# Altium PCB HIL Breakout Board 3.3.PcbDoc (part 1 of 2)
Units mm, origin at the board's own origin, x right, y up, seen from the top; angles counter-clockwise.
Board outline 262.51 x 133.53 mm, 4 copper layers (Top Layer, InternalPlane, Power, Bottom Layer); 38 components, 129 nets, 1004 pads, 22 vias.
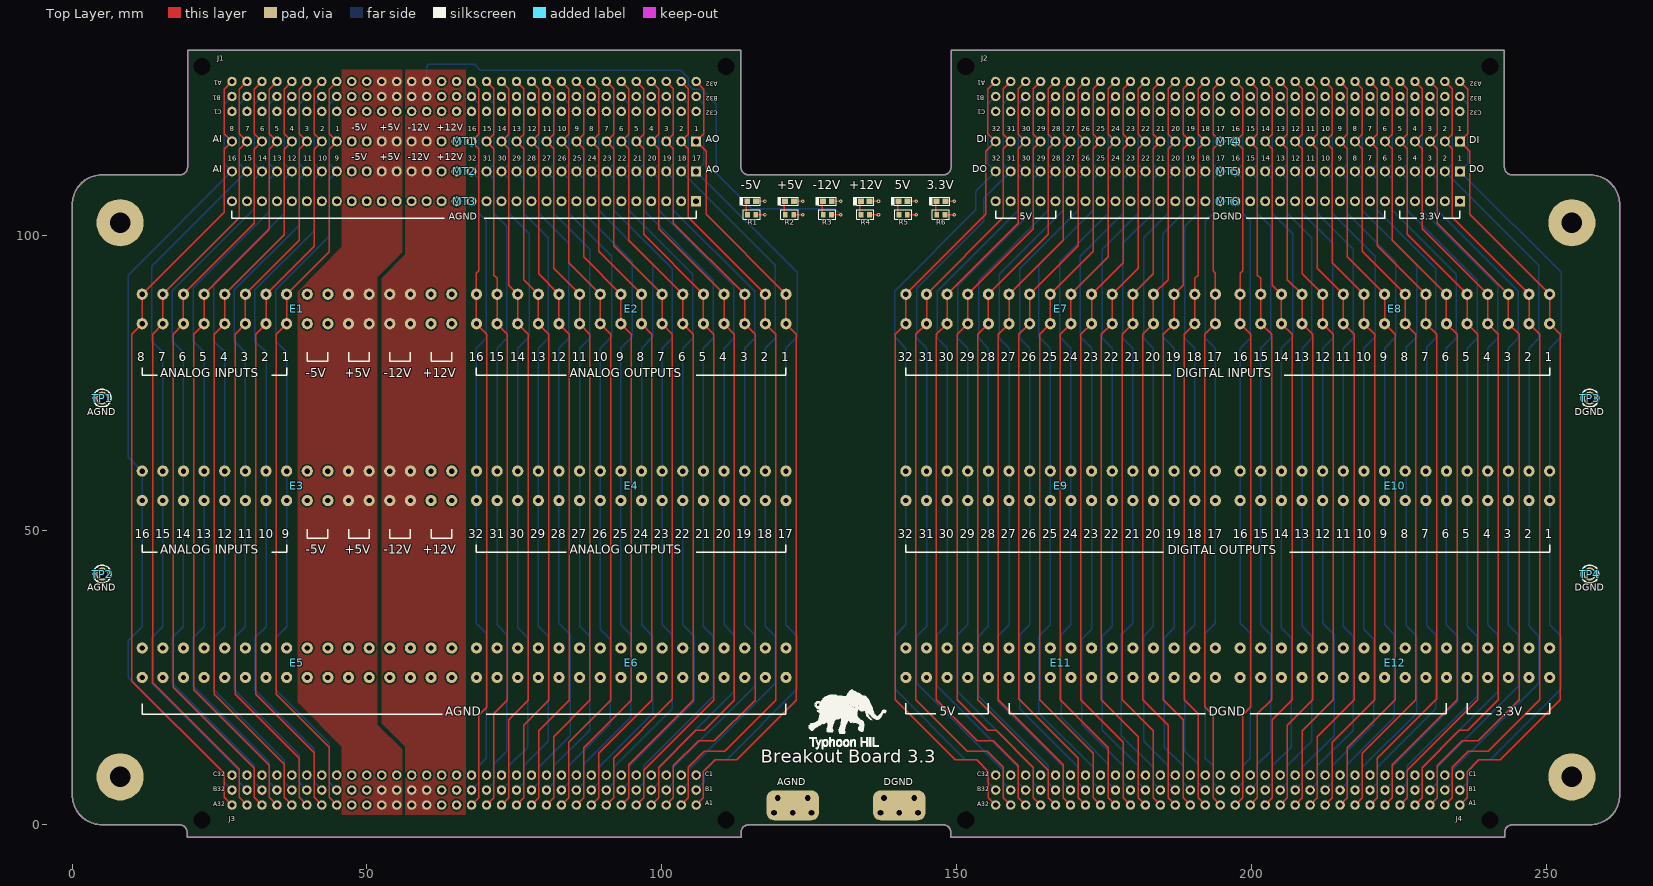
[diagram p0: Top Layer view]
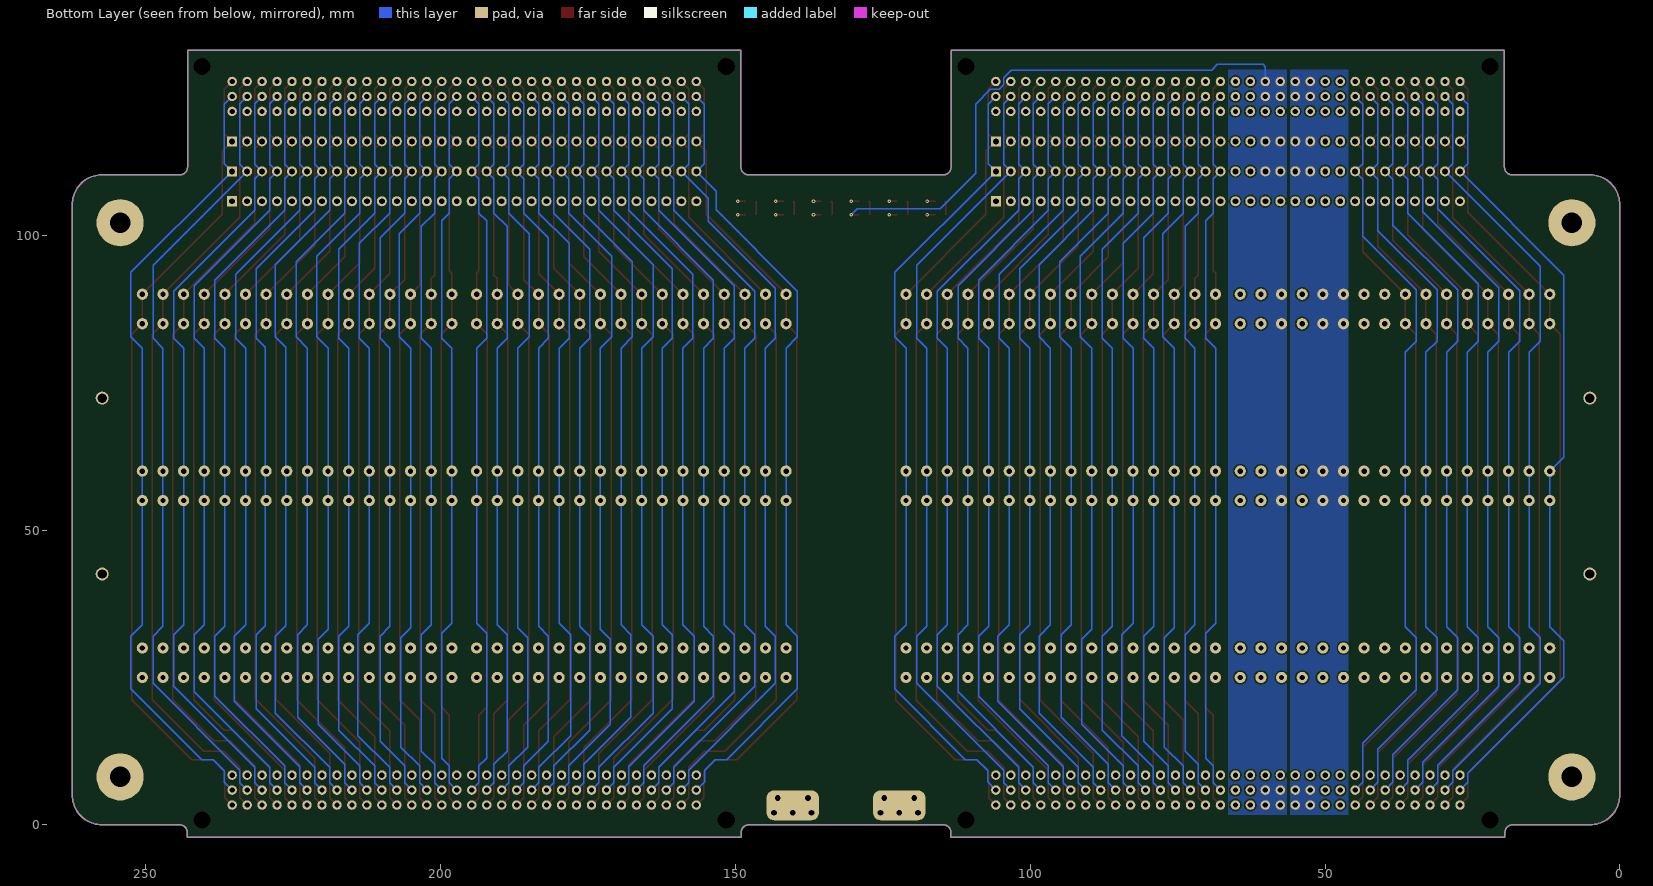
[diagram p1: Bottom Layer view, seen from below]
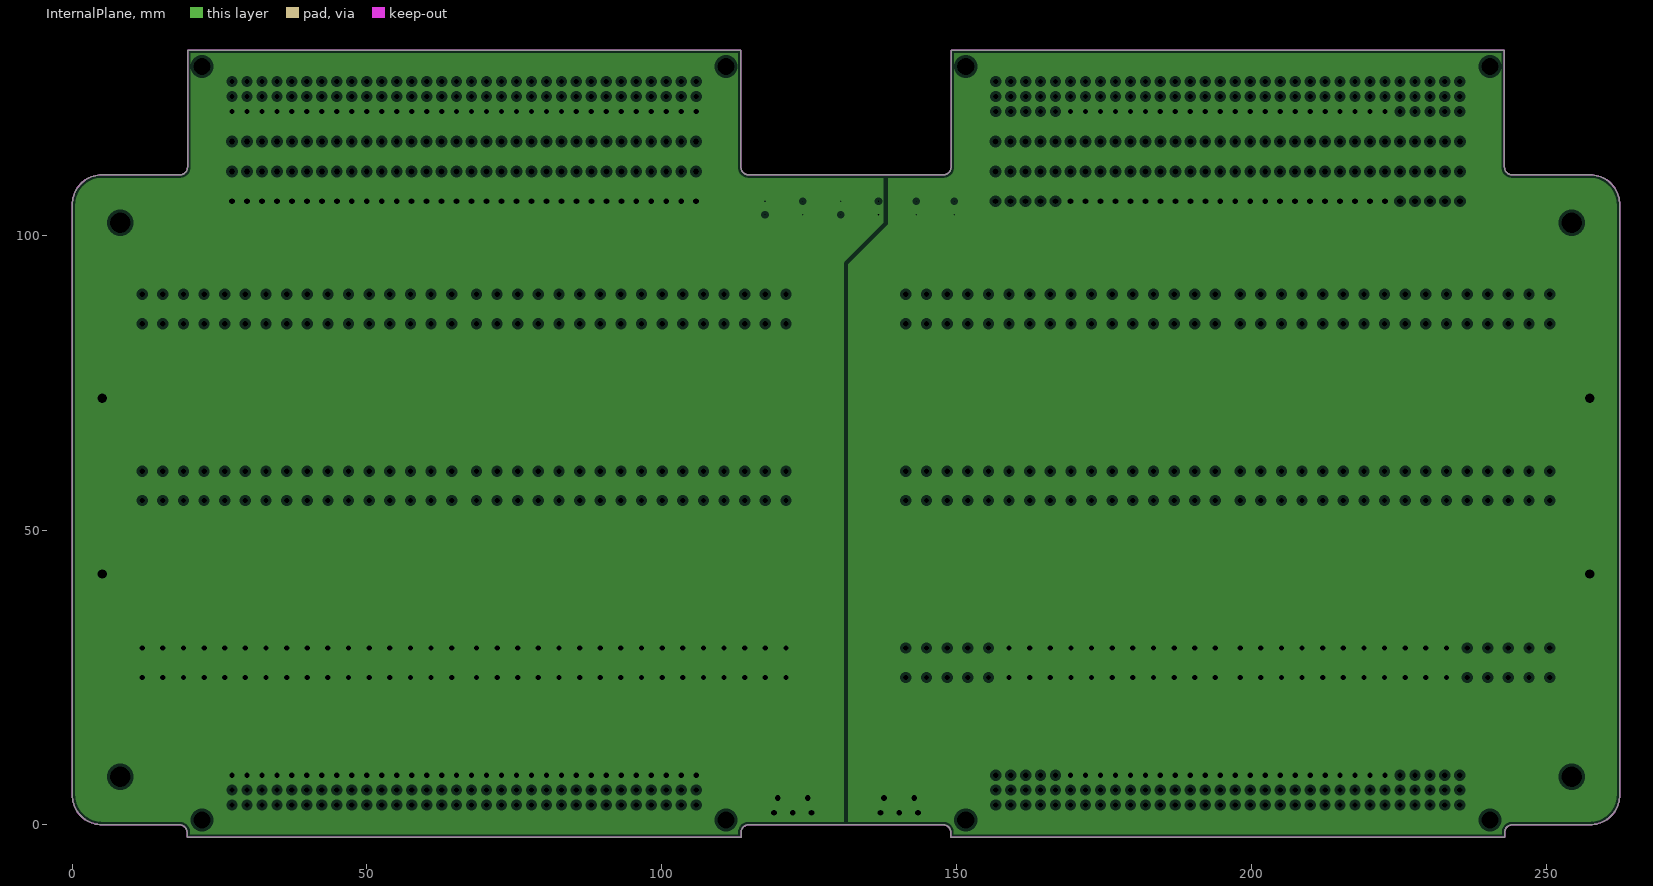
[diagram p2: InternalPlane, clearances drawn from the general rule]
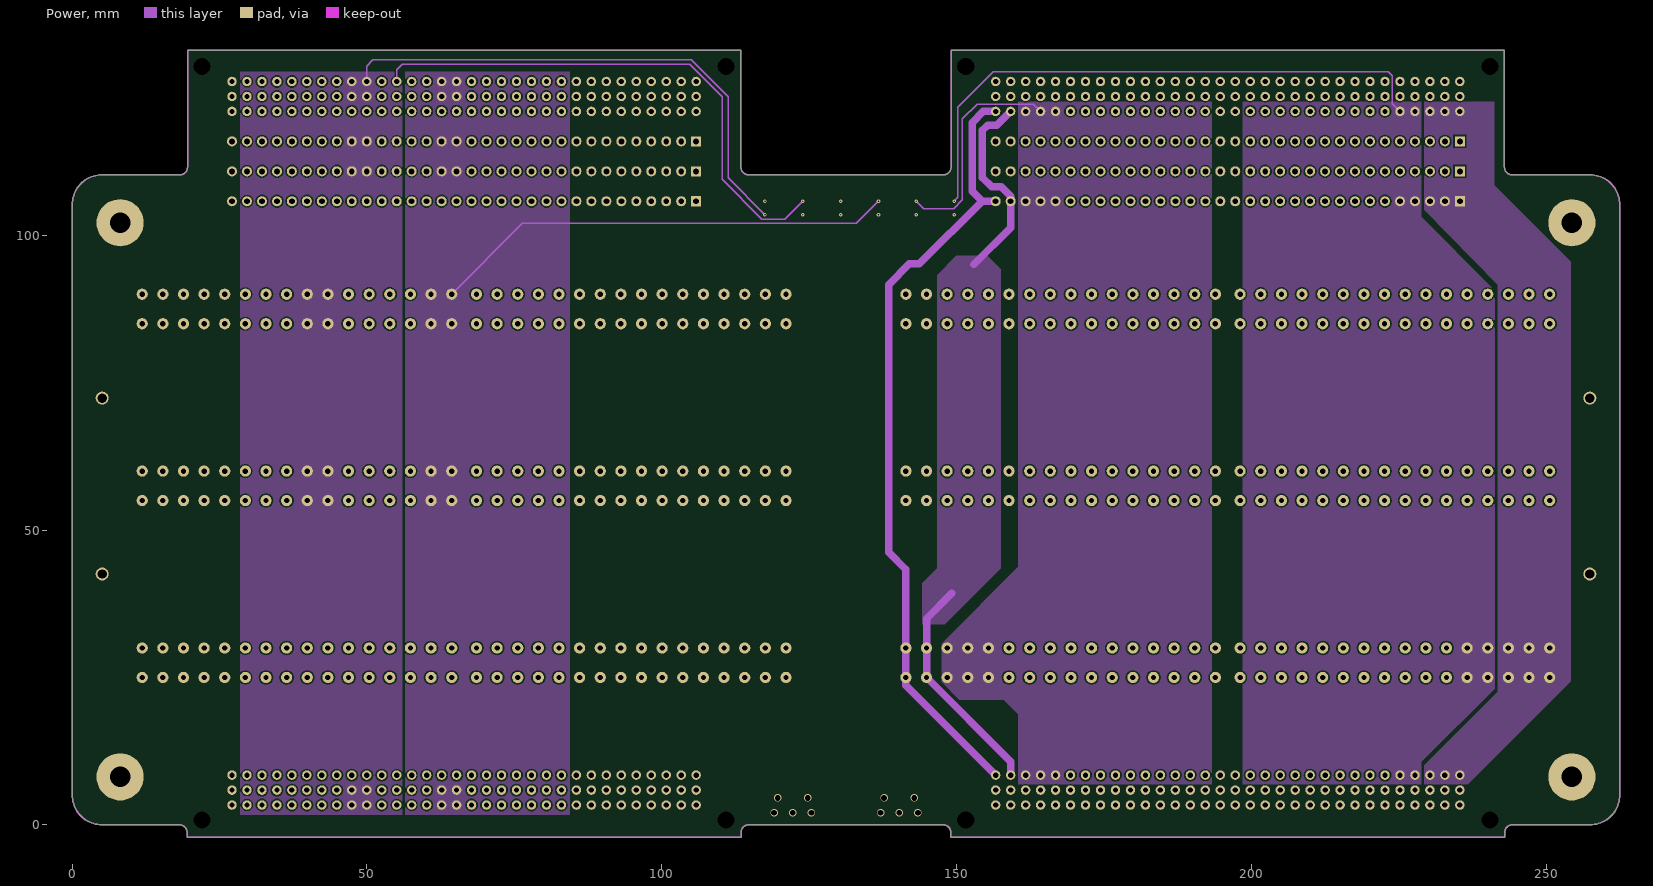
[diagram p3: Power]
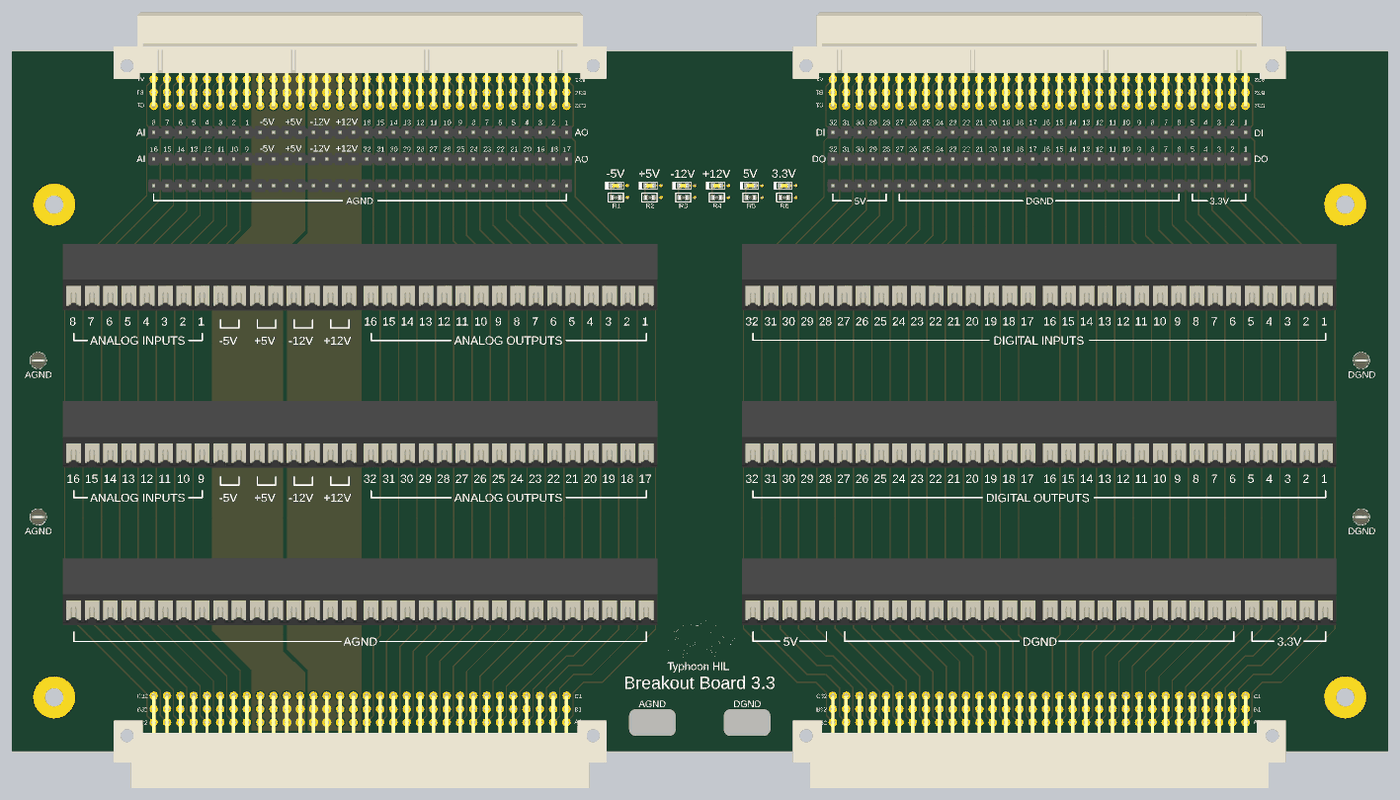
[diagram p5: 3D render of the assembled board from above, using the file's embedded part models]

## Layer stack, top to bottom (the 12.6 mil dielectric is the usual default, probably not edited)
Top Solder: solder mask 0.0102, Solder Resist, Dk 3.5
Top Layer: signal copper 0.0356
Dielectric1: core 0.32, FR-4, Dk 4.8
InternalPlane: plane copper 0.0356, net (Multiple Nets)
Dielectric3: prepreg 0.32, FR-4, Dk 4.8
Power: signal copper 0.0356
Dielectric2: core 0.32, FR-4, Dk 4.8
Bottom Layer: signal copper 0.0356
Bottom Solder: solder mask 0.0102, Solder Resist, Dk 3.5

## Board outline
5.08,0 18.212,0 cw(c18.212,-1.27) 19.482,-1.27 19.482,-2.134 113.462,-2.134 113.462,-1.27 cw(c114.732,-1.27) 114.732,0 147.752,0 cw(c147.752,-1.27) 149.022,-1.27 149.022,-2.134 243.002,-2.134 243.002,-1.27 cw(c244.272,-1.27) 244.272,0 257.429,0 ccw(c257.429,5.08) 262.509,5.08 262.509,105.181 ccw(c257.429,105.181) 257.429,110.261 244.221,110.261 cw(c244.221,111.531) 242.951,111.531 242.951,131.394 149.073,131.394 149.073,111.531 cw(c147.803,111.531) 147.803,110.261 114.704,110.261 114.706,110.261 cw(c114.706,111.531) 113.436,111.531 113.436,131.394 19.558,131.394 19.558,111.531 cw(c18.288,111.531) 18.288,110.261 5.08,110.261 ccw(c5.08,105.186) 0.005,105.186 0,105.186 0,5.08 ccw(c5.08,5.08)

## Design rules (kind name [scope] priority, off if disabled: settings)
Clearance [All] p1: gap=0.254 ignorepadtopadclearanceinfootprint=FALSE
HoleSize [All] p1: absolutevalues=TRUE maxlimit=5.08 minlimit=0.254 maxpercent=80.000 minpercent=20.000
PlaneClearance [All] p1: clearance=0.508
PlaneConnect [All] p1: planeconnectstyle=Direct reliefexpansion=0.508 reliefentries=4 reliefconductorwidth=0.254 reliefairgap=0.254
PolygonConnect [All] p1: connectstyle=Direct reliefconductorwidth=0.254 reliefentries=4 polygonreliefangle="90 Angle" airgapwidth=0.254
RoutingVias [All] p1: holewidth=0.3 width=0.6 viastyle="Through Hole" minholewidth=0.3 minwidth=0.6 maxholewidth=0.5 maxwidth=1
SilkToSilkClearance [All] p1: silktosilkclearance=0.127
SilkToSolderMaskClearance SilkscreenOverComponentPads [IsPad] p1: minsilkscreentomaskgap=0.025 clearancetoexposedcopper=TRUE
SolderMaskExpansion SolderMaskExpansion_Via [IsVia] p1: expansion=-25.4 istentingtop=FALSE
SolderMaskExpansion [All] p2: expansion=0.102 istentingtop=FALSE
UnRoutedNet [All] p1: checkbadconnections=TRUE
Width [All] p1: maxlimit=1.27 minlimit=0.254 preferedwidth=0.254
24 further rules are at their usual default settings.

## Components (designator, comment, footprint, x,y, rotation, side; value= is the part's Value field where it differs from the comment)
3.3V "LW Q38G-Q2OO-3K5L-1" 0603N 147.36,105.772 r0 top
5V "LW Q38G-Q2OO-3K5L-1" 0603N 140.938,105.772 r0 top
+5V "LW Q38G-Q2OO-3K5L-1" 0603N 121.672,105.772 r0 top
+12V "LW Q38G-Q2OO-3K5L-1" 0603N 134.516,105.772 r0 top
-5V "LW Q38G-Q2OO-3K5L-1" 0603N 115.25,105.772 r0 top
-12V "LW Q38G-Q2OO-3K5L-1" 0603N 128.094,105.772 r0 top
E1 "1885790000" LSF_SMT_3_5_135_16 38.122,88.25 r0 top locked
E2 "1885790000" LSF_SMT_3_5_135_16 94.822,88.25 r0 top locked
E3 "1885790000" LSF_SMT_3_5_135_16 38.122,58.25 r0 top
E4 "1885790000" LSF_SMT_3_5_135_16 94.822,58.25 r0 top locked
E5 "1885790000" LSF_SMT_3_5_135_16 38.122,28.25 r0 top locked
E6 "1885790000" LSF_SMT_3_5_135_16 94.822,28.25 r0 top locked
E7 "1885790000" LSF_SMT_3_5_135_16 167.662,88.25 r0 top locked
E8 "1885790000" LSF_SMT_3_5_135_16 224.362,88.25 r0 top locked
E9 "1885790000" LSF_SMT_3_5_135_16 167.662,58.25 r0 top locked
E10 "1885790000" LSF_SMT_3_5_135_16 224.362,58.25 r0 top locked
E11 "1885790000" LSF_SMT_3_5_135_16 167.662,28.25 r0 top locked
E12 "1885790000" LSF_SMT_3_5_135_16 224.362,28.25 r0 top locked
J1 "DIN41612 96F R" "HARTING DIN41612 96F R" 27.102,126.092 r180 top locked
J2 "DIN41612 96F R" "HARTING DIN41612 96F R" 156.642,126.092 r180 top locked
J3 "DIN41612 96M R" "HARTING DIN41612 96M R" 105.842,3.354 r0 top locked
J4 "DIN41612 96M R" "HARTING DIN41612 96M R" 235.382,3.354 r0 top locked
MT1 "Header 1x32" HEADER1X32 105.842,115.932 r180 top locked
MT2 "Header 1x32" HEADER1X32 105.842,110.852 r180 top locked
MT3 "Header 1x32" HEADER1X32 105.842,105.772 r180 top locked
MT4 "Header 1x32" HEADER1X32 235.382,115.932 r180 top locked
MT5 "Header 1x32" HEADER1X32 235.382,110.852 r180 top locked
MT6 "Header 1x32" HEADER1X32 235.382,105.772 r180 top locked
R1 "2K2" RESC1608X06N 115.25,103.5 r180 top
R2 "2K2" RESC1608X06N 121.672,103.5 r180 top
R3 "10K" RESC1608X06N 128.094,103.5 r180 top
R4 "10K" RESC1608X06N 134.516,103.5 r180 top
R5 "2K2" RESC1608X06N 140.938,103.5 r180 top
R6 "820R" RESC1608X06N 147.36,103.5 r180 top
TP1 "1.6mm hole, Qty.: 1PC, 2.4mm MAX PCB thickness" "TEST POINT 1.6mm HOLE" 5.08,72.39 r0 top
TP2 "1.6mm hole, Qty.: 1PC, 2.4mm MAX PCB thickness" "TEST POINT 1.6mm HOLE" 5.08,42.545 r0 top
TP3 "1.6mm hole, Qty.: 1PC, 2.4mm MAX PCB thickness" "TEST POINT 1.6mm HOLE" 257.429,72.39 r0 top
TP4 "1.6mm hole, Qty.: 1PC, 2.4mm MAX PCB thickness" "TEST POINT 1.6mm HOLE" 257.429,42.545 r0 top

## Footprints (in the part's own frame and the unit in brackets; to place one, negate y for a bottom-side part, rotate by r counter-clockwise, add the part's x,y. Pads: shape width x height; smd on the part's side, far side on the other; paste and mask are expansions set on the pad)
0603N [mm] "Chip Diode, DIOC1608X02N,2-Leads, Body 1.60x0.80mm, IPC Medium Density"
  rect 1x0.95 smd: 1(-0.75,0) 2(0.75,0)
  silkscreen extent -2.05,-0.74 1.47,0.74, body extent -0.81,-0.4 0.81,0.4, height 0.6
"HARTING DIN41612 96F R" [mm] "R096FS-3,0C1-2, PN: 09732966801"
  round 1.6 hole 0.9 mask+0.05: A1(0,0) A2(-2.54,0) A3(-5.08,0) A4(-7.62,0) A5(-10.16,0) A6(-12.7,0) A7(-15.24,0) A8(-17.78,0) A9(-20.32,0) A10(-22.86,0) A11(-25.4,0) A12(-27.94,0) A13(-30.48,0) A14(-33.02,0) A15(-35.56,0) A16(-38.1,0) A17(-40.64,0) A18(-43.18,0) A19(-45.72,0) A20(-48.26,0) A21(-50.8,0) A22(-53.34,0) A23(-55.88,0) A24(-58.42,0) A25(-60.96,0) A26(-63.5,0) A27(-66.04,0) A28(-68.58,0) A29(-71.12,0) A30(-73.66,0) A31(-76.2,0) A32(-78.74,0) B1(0,2.54) B2(-2.54,2.54) B3(-5.08,2.54) B4(-7.62,2.54) B5(-10.16,2.54) B6(-12.7,2.54) B7(-15.24,2.54) B8(-17.78,2.54) B9(-20.32,2.54) B10(-22.86,2.54) B11(-25.4,2.54) B12(-27.94,2.54) B13(-30.48,2.54) B14(-33.02,2.54) B15(-35.56,2.54) B16(-38.1,2.54) B17(-40.64,2.54) B18(-43.18,2.54) B19(-45.72,2.54) B20(-48.26,2.54) B21(-50.8,2.54) B22(-53.34,2.54) B23(-55.88,2.54) B24(-58.42,2.54) B25(-60.96,2.54) B26(-63.5,2.54) B27(-66.04,2.54) B28(-68.58,2.54) B29(-71.12,2.54) B30(-73.66,2.54) B31(-76.2,2.54) B32(-78.74,2.54) C1(0,5.08) C2(-2.54,5.08) C3(-5.08,5.08) C4(-7.62,5.08) C5(-10.16,5.08) C6(-12.7,5.08) C7(-15.24,5.08) C8(-17.78,5.08) C9(-20.32,5.08) C10(-22.86,5.08) C11(-25.4,5.08) C12(-27.94,5.08) C13(-30.48,5.08) C14(-33.02,5.08) C15(-35.56,5.08) C16(-38.1,5.08) C17(-40.64,5.08) C18(-43.18,5.08) C19(-45.72,5.08) C20(-48.26,5.08) C21(-50.8,5.08) C22(-53.34,5.08) C23(-55.88,5.08) C24(-58.42,5.08) C25(-60.96,5.08) C26(-63.5,5.08) C27(-66.04,5.08) C28(-68.58,5.08) C29(-71.12,5.08) C30(-73.66,5.08) C31(-76.2,5.08) C32(-78.74,5.08)
  round 0 hole 2.9 unplated mask+1.5: ""(-83.82,-2.54) ""(5.08,-2.54)
  body extent -86.37,-12.74 7.63,5.39, height 9.1
"HARTING DIN41612 96M R" [mm] "C096MS-3,0C1-1, PN: 09031962921"
  round 1.6 hole 0.9 mask+0.05: A1(0,0) A2(-2.54,0) A3(-5.08,0) A4(-7.62,0) A5(-10.16,0) A6(-12.7,0) A7(-15.24,0) A8(-17.78,0) A9(-20.32,0) A10(-22.86,0) A11(-25.4,0) A12(-27.94,0) A13(-30.48,0) A14(-33.02,0) A15(-35.56,0) A16(-38.1,0) A17(-40.64,0) A18(-43.18,0) A19(-45.72,0) A20(-48.26,0) A21(-50.8,0) A22(-53.34,0) A23(-55.88,0) A24(-58.42,0) A25(-60.96,0) A26(-63.5,0) A27(-66.04,0) A28(-68.58,0) A29(-71.12,0) A30(-73.66,0) A31(-76.2,0) A32(-78.74,0) B1(0,2.54) B2(-2.54,2.54) B3(-5.08,2.54) B4(-7.62,2.54) B5(-10.16,2.54) B6(-12.7,2.54) B7(-15.24,2.54) B8(-17.78,2.54) B9(-20.32,2.54) B10(-22.86,2.54) B11(-25.4,2.54) B12(-27.94,2.54) B13(-30.48,2.54) B14(-33.02,2.54) B15(-35.56,2.54) B16(-38.1,2.54) B17(-40.64,2.54) B18(-43.18,2.54) B19(-45.72,2.54) B20(-48.26,2.54) B21(-50.8,2.54) B22(-53.34,2.54) B23(-55.88,2.54) B24(-58.42,2.54) B25(-60.96,2.54) B26(-63.5,2.54) B27(-66.04,2.54) B28(-68.58,2.54) B29(-71.12,2.54) B30(-73.66,2.54) B31(-76.2,2.54) B32(-78.74,2.54) C1(0,5.08) C2(-2.54,5.08) C3(-5.08,5.08) C4(-7.62,5.08) C5(-10.16,5.08) C6(-12.7,5.08) C7(-15.24,5.08) C8(-17.78,5.08) C9(-20.32,5.08) C10(-22.86,5.08) C11(-25.4,5.08) C12(-27.94,5.08) C13(-30.48,5.08) C14(-33.02,5.08) C15(-35.56,5.08) C16(-38.1,5.08) C17(-40.64,5.08) C18(-43.18,5.08) C19(-45.72,5.08) C20(-48.26,5.08) C21(-50.8,5.08) C22(-53.34,5.08) C23(-55.88,5.08) C24(-58.42,5.08) C25(-60.96,5.08) C26(-63.5,5.08) C27(-66.04,5.08) C28(-68.58,5.08) C29(-71.12,5.08) C30(-73.66,5.08) C31(-76.2,5.08) C32(-78.74,5.08)
  round 0 hole 2.9 unplated mask+1.5: ""(-83.82,-2.54) ""(5.08,-2.54)
  body extent -86.37,-12.64 7.63,5.39, height 9.35
HEADER1X32 [mm]
  rect 1.7x1.7 hole 1: 1(0,0)
  round 1.7 hole 1: 2(2.54,0) 3(5.08,0) 4(7.62,0) 5(10.16,0) 6(12.7,0) 7(15.24,0) 8(17.78,0) 9(20.32,0) 10(22.86,0) 11(25.4,0) 12(27.94,0) 13(30.48,0) 14(33.02,0) 15(35.56,0) 16(38.1,0) 17(40.64,0) 18(43.18,0) 19(45.72,0) 20(48.26,0) 21(50.8,0) 22(53.34,0) 23(55.88,0) 24(58.42,0) 25(60.96,0) 26(63.5,0) 27(66.04,0) 28(68.58,0) 29(71.12,0) 30(73.66,0) 31(76.2,0) 32(78.74,0)
  body extent -1.07,-1.21 79.81,1.2, height 8.18
LSF_SMT_3_5_135_16 [mm] "OMNIMATE Signal - Serie LSF  LSF-SMT 3.50/16/135 1.5"
  round 1.9 hole 0.9: A1(-26.25,-3.25) A1(-26.25,1.75) A2(-22.75,-3.25) A2(-22.75,1.75) A3(-19.25,-3.25) A3(-19.25,1.75) A4(-15.75,-3.25) A4(-15.75,1.75) A5(-12.25,-3.25) A5(-12.25,1.75) A6(-8.75,-3.25) A6(-8.75,1.75) A7(-5.25,-3.25) A7(-5.25,1.75) A8(-1.75,-3.25) A8(-1.75,1.75) A9(1.75,-3.25) A9(1.75,1.75) A10(5.25,-3.25) A10(5.25,1.75) A11(8.75,-3.25) A11(8.75,1.75) A12(12.25,-3.25) A12(12.25,1.75) A13(15.75,-3.25) A13(15.75,1.75) A14(19.25,-3.25) A14(19.25,1.75) A15(22.75,-3.25) A15(22.75,1.75) A16(26.25,-3.25) A16(26.25,1.75)
  body extent -28.37,-6.31 28.33,6.39, height 13.16
RESC1608X06N [mil] "Chip Resistor, 2-Leads, Body 1.6x0.8mm, IPC Medium Density"
  rect 32x38 smd: 1(-28,0) 2(28,0)
  silkscreen extent -57,-32 57,32, body extent -31,-15 31,16, height 18
"TEST POINT 1.6mm HOLE" [mm]
  round 2.2 hole 1.6: 1(0,0)
  silkscreen extent -1.5,-1.5 1.5,1.5, body extent -1.58,-1.59 1.58,1.59, height 5.59

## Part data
3.3V 5V +5V +12V -5V -12V: "Standard LED - SMD White Diffused 8200K, If=15mA, Vf=2.85V, Case: 0603", Manufacturer="OSRAM Opto Semiconductors", Supplier Part Number 1=720-LWQ38GQ2R23K5L1
E1 E2 E3 E4 E5 E6 E7 E8 E9 E10 E11 E12: library part LSF_SMT_3_5_135_16__3_5_BK_TU, "OMNIMATE Signal - series LSF", Manufacturer=Weidmüller, Rated_current_min_no_of_poles_TU_20_deg_C="17,5 A", Rated_current_use_group_B_UL_1059="12 A", Rated_voltage_for_surge_voltage_class_pollution_degree_II_2="320 V", Rated_voltage_use_group_B_UL_1059="300 V", UL_94_flammability_rating=V-0
J1 J2: library part "HARTING DIN41612 96F R", "Connectors, Female connector, Wave soldering termination, Rated current: ‌2 A, Contacts: 96, Angled, Copper alloy, Noble metal, Mating side, Sn over Ni, Termination side, Performance level: 2, acc. to IEC 60603-2, Coding: Coding with loss of contacts, PCB fixing: With fixing flange, Thermoplastic resin, glass-fibre filled, RAL 7032 (pebble grey)", Manufacturer=Harting, Manufacturer Code=09732966801, Supplier Part Number 1=617-09-73-296-6801
J3 J4: library part "HARTING DIN41612 96M R", "96 pin ABC, RIGHT ANGLE, MALE", Manufacturer=Harting, Manufacturer Code=09031962921, Supplier Part Number 1=617-09-03-196-2921
MT1 MT2 MT3 MT4 MT5 MT6: "BOARD-BOARD CONN, HEADER, 32WAY, 1ROW", Manufacturer=Harwin, Manufacturer Code=M20-9773246, Supplier Part Number 1=855-M20-9773246
R1 R2 R5: library part "2K2 1% 0.1W", "2K2 1% 0.1W RESC1608X06", Manufacturer=Panasonic, Manufacturer Code=ERJ-3EKF2201V, Supplier Part Number 1=667-ERJ-3EKF2201V
R3 R4: library part "10K 1% 0.1W", "10K 1% 0.1W RESC1608X06", Manufacturer=Panasonic, Manufacturer Code=ERJ-3EKF1002V, Supplier Part Number 1=667-ERJ-3EKF1002V
R6: library part "820R 1% 0.1W", "820R 1% 0.1W RESC1608X06", Manufacturer=Panasonic, Manufacturer Code=ERJ-3EKF8200V, Supplier Part Number 1=667-ERJ-3EKF8200V
TP1 TP2 TP3 TP4: library part "Test Point", "MAX PCB thickness: 2.4mm; Mounting hole size: 1.6mm; Qty: 1PCS", Manufacturer="Keystone Electronics", Manufacturer Code=5006, Supplier Part Number 1=534-5006

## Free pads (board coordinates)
  rrect50% 8.89x5.08 smd: 0(122.225,3.31) 0(140.284,3.31)
  rrect50% 8.89x5.08 smd far side: 0(122.225,3.31) 0(140.284,3.31)
  round 8 hole 3.5: ""(8.128,8.128) ""(8.128,102.138) ""(254.381,8.128) ""(254.381,102.138)

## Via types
v1: diameter 0.6, hole 0.3, Top Layer to Bottom Layer, 12 vias
v2: diameter 1.27, hole 1, Top Layer to Bottom Layer, 10 vias

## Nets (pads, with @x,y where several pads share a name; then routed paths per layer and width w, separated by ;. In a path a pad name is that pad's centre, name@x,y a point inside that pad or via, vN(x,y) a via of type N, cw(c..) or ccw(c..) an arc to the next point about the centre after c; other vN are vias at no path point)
3.3VDOUT: 3.3V.2 E12.A12 E12.A13 J2.C28 J2.C29 J4.C4 J4.C5 MT6.4 MT6.5 | length 100.6
  Top Layer w0.254: 3.3V.2@148.26,105.772 v1(149.611,105.772)
  Power w0.254: v1(149.611,105.772) 150.25,106.411 150.25,121.75 156.25,127.75 223.25,127.75 223.913,127.087 223.913,122.321 J2.C28@225.222,121.012
3.3VDOUT_1: E12.A14 E12.A15 E12.A16 J2.C30 J2.C31 J2.C32 J4.C1 J4.C2 J4.C3 MT6.1 MT6.2 MT6.3
5VDOUT: 5V.2 E11.A3 E11.A4 E11.A5 J2.C3 J2.C4 J2.C5 J4.C28 J4.C29 J4.C30 MT6.28 MT6.29 MT6.30 | length 38.9
  Top Layer w0.254: 5V.2@141.838,105.772 v1(143.189,105.772)
  Power w0.254: v1(143.189,105.772) 144.461,104.5 149.5,104.5 151,106 151,119.75 153.5,122.25 163.024,122.25 J2.C4@164.262,121.012
15VDOUT: E11.A2 J2.C2 J4.C31 MT6.31 | length 72.9
  Power w1.27: 149.225,39.25 144.912,34.937 E11.A2@144.912,30 E11.A2@144.912,25 159.182,10.73 J4.C31@159.182,8.434 ; 152.931,95.044 159.182,101.295 MT6.31@159.182,105.772 159.182,106.655 157.607,108.229 155.956,108.229 154.407,109.779 154.407,117.805 155.27,118.669 156.838,118.669 J2.C2@159.182,121.012
24VDOUT: E11.A1 J2.C1 J4.C32 MT6.32 | length 133.5
  Power w1.27: J4.C32@156.642,8.434 141.412,23.664 E11.A1@141.412,25 E11.A1@141.412,30 141.412,43.313 138.475,46.25 138.475,91.593 142.019,95.138 143.695,95.138 154.33,105.772 ; MT6.32@156.642,105.772 154.33,105.772 ; J2.C1@156.642,121.012 154.54,121.012 152.654,119.126 152.654,107.448 154.33,105.772
+5VOUT: +5V.2 E1.A11 E1.A12 E3.A11 E3.A12 J1.A11 J1.A12 J1.B11 J1.B12 J3.A21 J3.A22 J3.B21 J3.B22 MT1.21 MT1.22 MT2.21 MT2.22 | length 92.9
  Top Layer w0.254: +5V.2@122.572,105.772 v1(123.923,105.772)
  Power w0.254: J1.A12@55.042,126.092 55.042,128.042 56,129 104.75,129 110.25,123.5 110.25,109.485 116.985,102.75 120.901,102.75 v1(123.923,105.772)
+12VOUT: +12V.2 E1.A15 E1.A16 E3.A15 E3.A16 J1.A15 J1.A16 J1.B15 J1.B16 J3.A17 J3.A18 J3.B17 J3.B18 MT1.17 MT1.18 MT2.17 MT2.18 | length 80.3
  Top Layer w0.254: +12V.2@135.416,105.772 v1(136.767,105.772)
  Power w0.254: E1.A16@64.372,90 76.372,102 132.995,102 v1(136.767,105.772)
-5VOUT: E1.A9 E1.A10 E3.A9 E3.A10 J1.A9 J1.A10 J1.B9 J1.B10 J3.A23 J3.A24 J3.B23 J3.B24 MT1.23 MT1.24 MT2.23 MT2.24 R1.1 | length 90.9
  Top Layer w0.254: R1.1@116.15,103.5 v1(117.501,103.5)
  Power w0.254: J1.A10@49.962,126.092 49.962,128.712 51,129.75 105,129.75 111.25,123.5 111.25,109.751 v1(117.501,103.5)
-12VOUT: E1.A13 E1.A14 E3.A13 E3.A14 J1.A13 J1.A14 J1.B13 J1.B14 J3.A19 J3.A20 J3.B19 J3.B20 MT1.19 MT1.20 MT2.19 MT2.20 R3.1 | length 92.4
  Top Layer w0.254: R3.1@128.994,103.5 v1(130.345,103.5)
  Bottom Layer w0.254: J1.A14@60.122,126.092 60.122,128.622 60.5,129 68.25,129 69.25,128 103.25,128 104.5,126.75 104.5,125.5 105.25,124.75 106.75,124.75 109.25,122.25 109.25,110.5 115.25,104.5 129.345,104.5 v1(130.345,103.5)
AGND: -5V.2 -12V.2 E5.A1 E5.A2 E5.A3 E5.A4 E5.A5 E5.A6 E5.A7 E5.A8 E5.A9 E5.A10 E5.A11 E5.A12 E5.A13 E5.A14 E5.A15 E5.A16 E6.A1 E6.A2 E6.A3 E6.A4 E6.A5 E6.A6 E6.A7 E6.A8 E6.A9 E6.A10 E6.A11 E6.A12 E6.A13 E6.A14 E6.A15 E6.A16 J1.C1 J1.C2 J1.C3 J1.C4 J1.C5 J1.C6 J1.C7 J1.C8 J1.C9 J1.C10 J1.C11 J1.C12 J1.C13 J1.C14 J1.C15 J1.C16 J1.C17 J1.C18 J1.C19 J1.C20 J1.C21 J1.C22 J1.C23 J1.C24 J1.C25 J1.C26 J1.C27 J1.C28 J1.C29 J1.C30 J1.C31 J1.C32 J3.C1 J3.C2 J3.C3 J3.C4 J3.C5 J3.C6 J3.C7 J3.C8 J3.C9 J3.C10 J3.C11 J3.C12 J3.C13 J3.C14 J3.C15 J3.C16 J3.C17 J3.C18 J3.C19 J3.C20 J3.C21 J3.C22 J3.C23 J3.C24 J3.C25 J3.C26 J3.C27 J3.C28 J3.C29 J3.C30 J3.C31 J3.C32 MT3.1 MT3.2 MT3.3 MT3.4 MT3.5 MT3.6 MT3.7 MT3.8 MT3.9 MT3.10 MT3.11 MT3.12 MT3.13 MT3.14 MT3.15 MT3.16 MT3.17 MT3.18 MT3.19 MT3.20 MT3.21 MT3.22 MT3.23 MT3.24 MT3.25 MT3.26 MT3.27 MT3.28 MT3.29 MT3.30 MT3.31 MT3.32 pad.0@122.225,3.31 R2.1 R4.1 TP1.1 TP2.1 | length 5.4
  Top Layer w0.254: -5V.2@116.15,105.772 v1(117.501,105.772) ; R2.1@122.572,103.5 v1(123.923,103.5) ; -12V.2@128.994,105.772 v1(130.345,105.772) ; R4.1@135.416,103.5 v1(136.767,103.5)
  other v2: 119.05,2.04 122.225,2.04 125.4,2.04 119.685,4.58 124.765,4.58
ANIN1: E1.A8 J1.A8 J3.A25 MT1.25 | length 132.3
  Top Layer w0.254: J3.A25@44.882,3.354 43.573,4.663 43.573,13.177 34.622,22.128 34.622,83.25 E1.A8@36.372,85 E1.A8@36.372,90 43.573,97.201 43.573,114.623 MT1.25@44.882,115.932 43.573,117.241 43.573,124.783 J1.A8@44.882,126.092
ANIN2: E1.A7 J1.A7 J3.A26 MT1.26 | length 133.1
  Top Layer w0.254: J3.A26@42.342,3.354 41.033,4.663 41.033,12.217 31.122,22.128 31.122,83.25 E1.A7@32.872,85 E1.A7@32.872,90 41.033,98.161 41.033,114.623 MT1.26@42.342,115.932 41.033,117.241 41.033,124.783 J1.A7@42.342,126.092
ANIN3: E1.A6 J1.A6 J3.A27 MT1.27 | length 133.9
  Top Layer w0.254: J3.A27@39.802,3.354 38.493,4.663 38.493,11.257 27.622,22.128 27.622,83.25 E1.A6@29.372,85 E1.A6@29.372,90 38.493,99.121 38.493,114.623 MT1.27@39.802,115.932 38.493,117.241 38.493,124.783 J1.A6@39.802,126.092
ANIN4: E1.A5 J1.A5 J3.A28 MT1.28 | length 134.7
  Top Layer w0.254: J3.A28@37.262,3.354 35.953,4.663 35.953,10.297 24.122,22.128 24.122,83.25 E1.A5@25.872,85 E1.A5@25.872,90 35.953,100.081 35.953,114.623 MT1.28@37.262,115.932 35.953,117.241 35.953,124.783 J1.A5@37.262,126.092
ANIN5: E1.A4 J1.A4 J3.A29 MT1.29 | length 135.5
  Top Layer w0.254: J3.A29@34.722,3.354 33.413,4.663 33.413,10.087 20.622,22.878 20.622,83.25 E1.A4@22.372,85 E1.A4@22.372,90 33.413,101.041 33.413,114.623 MT1.29@34.722,115.932 33.413,117.241 33.413,124.783 J1.A4@34.722,126.092
ANIN6: E1.A3 J1.A3 J3.A30 MT1.30 | length 136.3
  Top Layer w0.254: J3.A30@32.182,3.354 30.873,4.663 30.873,9.627 17.122,23.378 17.122,83.25 E1.A3@18.872,85 E1.A3@18.872,90 30.873,102.001 30.873,114.623 MT1.30@32.182,115.932 30.873,117.241 30.873,124.783 J1.A3@32.182,126.092
ANIN7: E1.A2 J1.A2 J3.A31 MT1.31 | length 137.1
  Top Layer w0.254: J3.A31@29.642,3.354 28.333,4.663 28.333,9.417 13.622,24.128 13.622,83.25 E1.A2@15.372,85 E1.A2@15.372,90 28.333,102.961 28.333,114.623 MT1.31@29.642,115.932 28.333,117.241 28.333,124.783 J1.A2@29.642,126.092
ANIN8: E1.A1 J1.A1 J3.A32 MT1.32 | length 137.9
  Top Layer w0.254: J3.A32@27.102,3.354 25.793,4.663 25.793,8.707 10.122,24.378 10.122,83.25 E1.A1@11.872,85 E1.A1@11.872,90 25.781,103.909 25.781,114.611 MT1.32@27.102,115.932 25.781,117.253 25.781,124.771 J1.A1@27.102,126.092
ANIN9: E3.A8 J1.B8 J3.B25 MT2.25 | length 128.9
  Bottom Layer w0.254: J3.B25@44.882,5.894 43.573,7.203 43.573,13.8 34.5,22.873 34.5,31.75 36.372,33.622 E3.A8@36.372,55 E3.A8@36.372,60 36.372,80.128 34.5,82 34.5,90.75 43.573,99.823 43.573,109.52 43.561,109.531 MT2.25@44.882,110.852 43.573,112.161 43.573,122.243 J1.B8@44.882,123.552
ANIN10: E3.A7 J1.B7 J3.B26 MT2.26 | length 129.7
  Bottom Layer w0.254: J3.B26@42.342,5.894 41.033,7.203 41.033,12.84 31,22.873 31,31.75 32.872,33.622 E3.A7@32.872,55 E3.A7@32.872,60 32.872,80.128 31,82 31,90.75 41.033,100.783 41.033,109.52 41.021,109.531 MT2.26@42.342,110.852 41.033,112.161 41.033,122.243 J1.B7@42.342,123.552
ANIN11: E3.A6 J1.B6 J3.B27 MT2.27 | length 130.5
  Bottom Layer w0.254: J3.B27@39.802,5.894 38.493,7.203 38.493,11.88 27.5,22.873 27.5,31.75 29.372,33.622 E3.A6@29.372,55 E3.A6@29.372,60 29.372,80.128 27.5,82 27.5,90.75 38.493,101.743 38.493,109.52 38.481,109.531 MT2.27@39.802,110.852 38.493,112.161 38.493,122.243 J1.B6@39.802,123.552
ANIN12: E3.A5 J1.B5 J3.B28 MT2.28 | length 131.3
  Bottom Layer w0.254: J3.B28@37.262,5.894 35.953,7.203 35.953,10.92 24,22.873 24,31.75 25.872,33.622 E3.A5@25.872,55 E3.A5@25.872,60 25.872,80.128 24,82 24,91.797 35.953,103.75 35.953,109.52 35.941,109.531 MT2.28@37.262,110.852 35.953,112.161 35.953,122.243 J1.B5@37.262,123.552
ANIN13: E3.A4 J1.B4 J3.B29 MT2.29 | length 132.1
  Bottom Layer w0.254: J3.B29@34.722,5.894 33.413,7.203 33.413,10.587 20.5,23.5 20.5,31.75 22.372,33.622 E3.A4@22.372,55 E3.A4@22.372,60 22.372,80.128 20.5,82 20.5,91.087 33.413,104 33.413,109.52 33.401,109.531 MT2.29@34.722,110.852 33.413,112.161 33.413,122.243 J1.B4@34.722,123.552
ANIN14: E3.A3 J1.B3 J3.B30 MT2.30 | length 132.9
  Bottom Layer w0.254: J3.B30@32.182,5.894 30.873,7.203 30.873,10.127 17,24 17,31.75 18.872,33.622 E3.A3@18.872,55 E3.A3@18.872,60 18.872,80.128 17,82 17,90.627 30.873,104.5 30.873,109.543 MT2.30@32.182,110.852 30.873,112.161 30.873,122.243 J1.B3@32.182,123.552
ANIN15: E3.A2 J1.B2 J3.B31 MT2.31 | length 133.7
  Bottom Layer w0.254: J3.B31@29.642,5.894 28.333,7.203 28.333,9.167 13.5,24 13.5,31.75 15.372,33.622 E3.A2@15.372,55 E3.A2@15.372,60 15.372,80.128 13.5,82 13.5,94.71 MT2.31@29.642,110.852 28.333,112.161 28.333,122.243 J1.B2@29.642,123.552
ANIN16: E3.A1 J1.B1 J3.B32 MT2.32 | length 135.3
  Bottom Layer w0.254: J3.B32@27.102,5.894 25.793,7.203 25.793,8.707 9.5,25 9.5,31.25 11.872,33.622 E3.A1@11.872,55 E3.A1@11.872,60 9.5,62.372 9.5,93.25 MT2.32@27.102,110.852 25.781,112.173 25.781,122.231 J1.B1@27.102,123.552
ANOUT1: E2.A16 J1.A32 J3.A1 MT1.1 | length 140
  Top Layer w0.254: J3.A1@105.842,3.354 107.073,4.585 107.073,9.025 109.048,11 112.692,11 122.822,21.13 122.822,83.25 E2.A16@121.072,85 E2.A16@121.072,90 107.524,103.548 107.524,114.25 MT1.1@105.842,115.932 107.151,117.241 107.151,124.783 J1.A32@105.842,126.092
ANOUT2: E2.A15 J1.A31 J3.A2 MT1.2 | length 139
  Top Layer w0.254: J3.A2@103.302,3.354 104.533,4.585 104.533,9.783 107.25,12.5 110.692,12.5 119.322,21.13 119.322,83.25 E2.A15@117.572,85 E2.A15@117.572,90 104.533,103.039 104.533,114.701 MT1.2@103.302,115.932 104.533,117.163 104.533,124.861 J1.A31@103.302,126.092
ANOUT3: E2.A14 J1.A30 J3.A3 MT1.3 | length 137.8
  Top Layer w0.254: J3.A3@100.762,3.354 101.993,4.585 101.993,9.993 106.25,14.25 108.942,14.25 115.822,21.13 115.822,83.25 E2.A14@114.072,85 E2.A14@114.072,90 101.993,102.079 101.993,114.701 MT1.3@100.762,115.932 101.993,117.163 101.993,124.861 J1.A30@100.762,126.092
ANOUT4: E2.A13 J1.A29 J3.A4 MT1.4 | length 136.3
  Top Layer w0.254: J3.A4@98.222,3.354 99.453,4.585 99.453,9.703 105.75,16 107.192,16 112.322,21.13 112.322,83.25 E2.A13@110.572,85 E2.A13@110.572,90 99.453,101.119 99.453,114.701 MT1.4@98.222,115.932 99.453,117.163 99.453,124.861 J1.A29@98.222,126.092
ANOUT5: E2.A12 J1.A28 J3.A5 MT1.5 | length 134.6
  Top Layer w0.254: J3.A5@95.682,3.354 96.913,4.585 96.913,9.221 108.822,21.13 108.822,83.25 E2.A12@107.072,85 E2.A12@107.072,90 96.913,100.159 96.913,114.701 MT1.5@95.682,115.932 96.913,117.163 96.913,124.861 J1.A28@95.682,126.092
ANOUT6: E2.A11 J1.A27 J3.A6 MT1.6 | length 133.8
  Top Layer w0.254: J3.A6@93.142,3.354 94.373,4.585 94.373,10.181 105.322,21.13 105.322,83.25 E2.A11@103.572,85 E2.A11@103.572,90 94.373,99.199 94.373,114.701 MT1.6@93.142,115.932 94.373,117.163 94.373,124.861 J1.A27@93.142,126.092
ANOUT7: E2.A10 J1.A26 J3.A7 MT1.7 | length 133.1
  Top Layer w0.254: J3.A7@90.602,3.354 91.833,4.585 91.833,11.333 101.822,21.322 101.822,83.25 E2.A10@100.072,85 E2.A10@100.072,90 91.833,98.239 91.833,114.701 MT1.7@90.602,115.932 91.833,117.163 91.833,124.861 J1.A26@90.602,126.092
ANOUT8: E2.A9 J1.A25 J3.A8 MT1.8 | length 132.3
  Top Layer w0.254: J3.A8@88.062,3.354 89.293,4.585 89.293,12.101 98.322,21.13 98.322,83.25 E2.A9@96.572,85 E2.A9@96.572,90 89.293,97.279 89.293,114.701 MT1.8@88.062,115.932 89.293,117.163 89.293,124.861 J1.A25@88.062,126.092
ANOUT9: E2.A8 J1.A24 J3.A9 MT1.9 | length 131.5
  Top Layer w0.254: J3.A9@85.522,3.354 86.753,4.585 86.753,13.061 94.822,21.13 94.822,83.25 E2.A8@93.072,85 E2.A8@93.072,90 86.753,96.319 86.753,114.701 MT1.9@85.522,115.932 86.753,117.163 86.753,124.861 J1.A24@85.522,126.092
ANOUT10: E2.A7 J1.A23 J3.A10 MT1.10 | length 130.7
  Top Layer w0.254: J3.A10@82.982,3.354 84.213,4.585 84.213,14.021 91.322,21.13 91.322,83.25 E2.A7@89.572,85 E2.A7@89.572,90 84.213,95.359 84.213,114.701 MT1.10@82.982,115.932 84.213,117.163 84.213,124.861 J1.A23@82.982,126.092
ANOUT11: E2.A6 J1.A22 J3.A11 MT1.11 | length 129.9
  Top Layer w0.254: J3.A11@80.442,3.354 81.673,4.585 81.673,14.981 87.822,21.13 87.822,83.25 E2.A6@86.072,85 E2.A6@86.072,90 81.673,94.399 81.673,114.701 MT1.11@80.442,115.932 81.673,117.163 81.673,124.861 J1.A22@80.442,126.092
ANOUT12: E2.A5 J1.A21 J3.A12 MT1.12 | length 129.1
  Top Layer w0.254: J3.A12@77.902,3.354 79.133,4.585 79.133,15.941 84.322,21.13 84.322,83.25 E2.A5@82.572,85 E2.A5@82.572,90 79.133,93.439 79.133,114.701 MT1.12@77.902,115.932 79.133,117.163 79.133,124.861 J1.A21@77.902,126.092
ANOUT13: E2.A4 J1.A20 J3.A13 MT1.13 | length 128.3
  Top Layer w0.254: J3.A13@75.362,3.354 76.593,4.585 76.593,16.901 80.822,21.13 80.822,83.25 E2.A4@79.072,85 E2.A4@79.072,90 76.593,92.479 76.593,114.701 MT1.13@75.362,115.932 76.593,117.163 76.593,124.861 J1.A20@75.362,126.092
ANOUT14: E2.A3 J1.A19 J3.A14 MT1.14 | length 127.5
  Top Layer w0.254: J3.A14@72.822,3.354 74.053,4.585 74.053,17.861 77.322,21.13 77.322,83.25 E2.A3@75.572,85 E2.A3@75.572,90 74.053,91.519 74.053,114.701 MT1.14@72.822,115.932 74.053,117.163 74.053,124.861 J1.A19@72.822,126.092
ANOUT15: E2.A2 J1.A18 J3.A15 MT1.15 | length 126.7
  Top Layer w0.254: J3.A15@70.282,3.354 71.513,4.585 71.513,18.821 73.822,21.13 73.822,83.25 E2.A2@72.072,85 E2.A2@72.072,90 72.072,92.691 71.513,93.25 71.513,114.701 MT1.15@70.282,115.932 71.513,117.163 71.513,124.861 J1.A18@70.282,126.092
ANOUT16: E2.A1 J1.A17 J3.A16 MT1.16 | length 126.2
  Top Layer w0.254: J3.A16@67.742,3.354 68.973,4.585 68.973,18.601 70.322,19.95 70.322,83.25 E2.A1@68.572,85 E2.A1@68.572,90 68.572,93.599 68.973,94 68.973,114.701 MT1.16@67.742,115.932 68.973,117.163 68.973,124.861 J1.A17@67.742,126.092
ANOUT17: E4.A16 J1.B32 J3.B1 MT2.1 | length 135.7
  Bottom Layer w0.254: J3.B1@105.842,5.894 107.25,7.302 107.25,9.25 109.052,11.052 111,11.052 123,23.052 123,32 121.072,33.928 E4.A16@121.072,55 E4.A16@121.072,60 121.072,80.822 123,82.75 123,93.694 107.151,109.543 MT2.1@105.842,110.852 107.151,112.161 107.151,122.243 J1.B32@105.842,123.552
ANOUT18: E4.A15 J1.B31 J3.B2 MT2.2 | length 133.3
  Bottom Layer w0.254: J3.B2@103.302,5.894 104.533,7.125 104.533,9.283 119.25,24 119.25,32 117.572,33.678 E4.A15@117.572,55 E4.A15@117.572,60 117.572,80.822 119.25,82.5 119.25,94.904 MT2.2@103.302,110.852 104.533,112.083 104.533,122.321 J1.B31@103.302,123.552
ANOUT19: E4.A14 J1.B30 J3.B3 MT2.3 | length 132.5
  Bottom Layer w0.254: J3.B3@100.762,5.894 101.993,7.125 101.993,9.75 115.75,23.507 115.75,32.25 114.072,33.928 E4.A14@114.072,55 E4.A14@114.072,60 114.072,80.822 115.75,82.5 115.75,90.493 101.993,104.25 101.993,109.621 MT2.3@100.762,110.852 101.993,112.083 101.993,122.321 J1.B30@100.762,123.552
ANOUT20: E4.A13 J1.B29 J3.B4 MT2.4 | length 131.7
  Bottom Layer w0.254: J3.B4@98.222,5.894 99.453,7.125 99.453,9.75 112.25,22.547 112.25,32.25 110.572,33.928 E4.A13@110.572,55 E4.A13@110.572,60 110.572,80.822 112.25,82.5 112.25,91.453 99.453,104.25 99.453,109.621 MT2.4@98.222,110.852 99.453,112.083 99.453,122.321 J1.B29@98.222,123.552
ANOUT21: E4.A12 J1.B28 J3.B5 MT2.5 | length 130.9
  Bottom Layer w0.254: J3.B5@95.682,5.894 96.913,7.125 96.913,10 108.75,21.837 108.75,32 107.072,33.678 E4.A12@107.072,55 E4.A12@107.072,60 107.072,80.822 108.75,82.5 108.75,92.413 96.913,104.25 96.913,109.621 MT2.5@95.682,110.852 96.913,112.083 96.913,122.321 J1.B28@95.682,123.552
ANOUT22: E4.A11 J1.B27 J3.B6 MT2.6 | length 130.3
  Bottom Layer w0.254: J3.B6@93.142,5.894 94.373,7.125 94.373,9.873 105.5,21 105.5,32 103.572,33.928 E4.A11@103.572,55 E4.A11@103.572,60 103.572,80.822 105.25,82.5 105.25,93.373 94.373,104.25 94.373,109.621 MT2.6@93.142,110.852 94.373,112.083 94.373,122.321 J1.B27@93.142,123.552
ANOUT23: E4.A10 J1.B26 J3.B7 MT2.7 | length 129.3
  Bottom Layer w0.254: J3.B7@90.602,5.894 91.833,7.125 91.833,9.75 101.75,19.667 101.75,32.25 100.072,33.928 E4.A10@100.072,55 E4.A10@100.072,60 100.072,80.822 101.75,82.5 101.75,94.333 91.833,104.25 91.833,109.621 MT2.7@90.602,110.852 91.833,112.083 91.833,122.321 J1.B26@90.602,123.552
ANOUT24: E4.A9 J1.B25 J3.B8 MT2.8 | length 128.9
  Bottom Layer w0.254: J3.B8@88.062,5.894 89.293,7.125 89.293,9.75 98.5,18.957 98.5,32 96.572,33.928 E4.A9@96.572,55 E4.A9@96.572,60 96.572,80.822 98.5,82.75 98.5,95.043 89.293,104.25 89.293,109.621 MT2.8@88.062,110.852 89.293,112.083 89.293,122.321 J1.B25@88.062,123.552
ANOUT25: E4.A8 J1.B24 J3.B9 MT2.9 | length 127.9
  Bottom Layer w0.254: J3.B9@85.522,5.894 86.753,7.125 86.753,10.25 94.75,18.247 94.75,32.25 93.072,33.928 E4.A8@93.072,55 E4.A8@93.072,60 93.072,80.822 95,82.75 95,95.503 86.753,103.75 86.753,109.621 MT2.9@85.522,110.852 86.753,112.083 86.753,122.321 J1.B24@85.522,123.552
ANOUT26: E4.A7 J1.B23 J3.B10 MT2.10 | length 127.1
  Bottom Layer w0.254: J3.B10@82.982,5.894 84.213,7.125 84.213,10 91.25,17.037 91.25,31.5 89.572,33.178 E4.A7@89.572,55 E4.A7@89.572,60 89.572,80.822 91.5,82.75 91.5,96.463 84.213,103.75 84.213,109.621 MT2.10@82.982,110.852 84.213,112.083 84.213,122.321 J1.B23@82.982,123.552
ANOUT27: E4.A6 J1.B22 J3.B11 MT2.11 | length 126.1
  Bottom Layer w0.254: J3.B11@80.442,5.894 81.673,7.125 81.673,10 87.75,16.077 87.75,32 86.072,33.678 E4.A6@86.072,55 E4.A6@86.072,60 86.072,80.822 87.75,82.5 87.75,97.673 81.673,103.75 81.673,109.621 MT2.11@80.442,110.852 81.673,112.083 81.673,122.321 J1.B22@80.442,123.552
ANOUT28: E4.A5 J1.B21 J3.B12 MT2.12 | length 125.5
  Bottom Layer w0.254: J3.B12@77.902,5.894 79.133,7.125 79.133,9.75 84.5,15.117 84.5,32.25 82.572,34.178 E4.A5@82.572,55 E4.A5@82.572,60 82.572,80.822 84.25,82.5 84.25,98.633 79.133,103.75 79.133,109.621 MT2.12@77.902,110.852 79.133,112.083 79.133,122.321 J1.B21@77.902,123.552
ANOUT29: E4.A4 J1.B20 J3.B13 MT2.13 | length 124.5
  Bottom Layer w0.254: J3.B13@75.362,5.894 76.593,7.125 76.593,10 80.75,14.157 80.75,32 79.072,33.678 E4.A4@79.072,55 E4.A4@79.072,60 79.072,80.822 80.75,82.5 80.75,99.593 76.593,103.75 76.593,109.621 MT2.13@75.362,110.852 76.593,112.083 76.593,122.321 J1.B20@75.362,123.552
ANOUT30: E4.A3 J1.B19 J3.B14 MT2.14 | length 123.9
  Bottom Layer w0.254: J3.B14@72.822,5.894 74.053,7.125 74.053,10 77.25,13.197 77.25,31.75 75.572,33.428 E4.A3@75.572,55 E4.A3@75.572,60 75.572,80.822 77.5,82.75 77.5,100.303 74.053,103.75 74.053,109.621 MT2.14@72.822,110.852 74.053,112.083 74.053,122.321 J1.B19@72.822,123.552
ANOUT31: E4.A2 J1.B18 J3.B15 MT2.15 | length 122.9
  Bottom Layer w0.254: J3.B15@70.282,5.894 71.513,7.125 71.513,10.263 73.75,12.5 73.75,32.25 72.072,33.928 E4.A2@72.072,55 E4.A2@72.072,60 72.072,80.822 73.75,82.5 73.75,101.513 71.513,103.75 71.513,109.621 MT2.15@70.282,110.852 71.513,112.083 71.513,122.321 J1.B18@70.282,123.552
ANOUT32: E4.A1 J1.B17 J3.B16 MT2.16 | length 122.1
  Bottom Layer w0.254: J3.B16@67.742,5.894 68.973,7.125 68.973,10 70.25,11.277 70.25,32.5 68.572,34.178 E4.A1@68.572,55 E4.A1@68.572,60 68.572,80.822 70.25,82.5 70.25,102.473 68.973,103.75 68.973,109.621 MT2.16@67.742,110.852 68.973,112.083 68.973,122.321 J1.B17@67.742,123.552
DGND: E11.A6 E11.A7 E11.A8 E11.A9 E11.A10 E11.A11 E11.A12 E11.A13 E11.A14 E11.A15 E11.A16 E12.A1 E12.A2 E12.A3 E12.A4 E12.A5 E12.A6 E12.A7 E12.A8 E12.A9 E12.A10 E12.A11 J2.C6 J2.C7 J2.C8 J2.C9 J2.C10 J2.C11 J2.C12 J2.C13 J2.C14 J2.C15 J2.C16 J2.C17 J2.C18 J2.C19 J2.C20 J2.C21 J2.C22 J2.C23 J2.C24 J2.C25 J2.C26 J2.C27 J4.C6 J4.C7 J4.C8 J4.C9 J4.C10 J4.C11 J4.C12 J4.C13 J4.C14 J4.C15 J4.C16 J4.C17 J4.C18 J4.C19 J4.C20 J4.C21 J4.C22 J4.C23 J4.C24 J4.C25 J4.C26 J4.C27 MT6.6 MT6.7 MT6.8 MT6.9 MT6.10 MT6.11 MT6.12 MT6.13 MT6.14 MT6.15 MT6.16 MT6.17 MT6.18 MT6.19 MT6.20 MT6.21 MT6.22 MT6.23 MT6.24 MT6.25 MT6.26 MT6.27 pad.0@140.284,3.31 R5.1 R6.1 TP3.1 TP4.1 | length 2.7
  Top Layer w0.254: R5.1@141.838,103.5 v1(143.189,103.5) ; R6.1@148.26,103.5 v1(149.611,103.5)
  other v2: 137.109,2.04 140.284,2.04 143.459,2.04 137.719,4.58 142.824,4.58
DI1: E8.A16 J2.A32 J4.A1 MT4.1 | length 140.1
  Top Layer w0.254: J4.A1@235.382,3.354 236.613,4.585 236.613,9.025 238.588,11 242.232,11 252.434,21.202 252.434,83.178 E8.A16@250.612,85 E8.A16@250.612,90 237.064,103.548 237.064,114.25 MT4.1@235.382,115.932 236.691,117.241 236.691,124.783 J2.A32@235.382,126.092
DI2: E8.A15 J2.A31 J4.A2 MT4.2 | length 139.1
  Top Layer w0.254: J4.A2@232.842,3.354 234.073,4.585 234.073,9.783 236.79,12.5 240.232,12.5 248.934,21.202 248.934,83.178 E8.A15@247.112,85 E8.A15@247.112,90 234.073,103.039 234.073,114.701 MT4.2@232.842,115.932 234.073,117.163 234.073,124.861 J2.A31@232.842,126.092
DI3: E8.A14 J2.A30 J4.A3 MT4.3 | length 137.9
  Top Layer w0.254: J4.A3@230.302,3.354 231.533,4.585 231.533,9.993 235.79,14.25 238.482,14.25 245.434,21.202 245.434,83.178 E8.A14@243.612,85 E8.A14@243.612,90 231.533,102.079 231.533,114.701 MT4.3@230.302,115.932 231.533,117.163 231.533,124.861 J2.A30@230.302,126.092
DI4: E8.A13 J2.A29 J4.A4 MT4.4 | length 136.3
  Top Layer w0.254: J4.A4@227.762,3.354 228.993,4.585 228.993,9.703 235.29,16 236.732,16 241.934,21.202 241.934,83.178 E8.A13@240.112,85 E8.A13@240.112,90 228.993,101.119 228.993,114.701 MT4.4@227.762,115.932 228.993,117.163 228.993,124.861 J2.A29@227.762,126.092
DI5: E8.A12 J2.A28 J4.A5 MT4.5 | length 134.7
  Top Layer w0.254: J4.A5@225.222,3.354 226.453,4.585 226.453,9.221 238.434,21.202 238.434,83.178 E8.A12@236.612,85 E8.A12@236.612,90 226.453,100.159 226.453,114.701 MT4.5@225.222,115.932 226.453,117.163 226.453,124.861 J2.A28@225.222,126.092
DI6: E8.A11 J2.A27 J4.A6 MT4.6 | length 133.9
  Top Layer w0.254: J4.A6@222.682,3.354 223.913,4.585 223.913,10.181 234.934,21.202 234.934,83.178 E8.A11@233.112,85 E8.A11@233.112,90 223.913,99.199 223.913,114.701 MT4.6@222.682,115.932 223.913,117.163 223.913,124.861 J2.A27@222.682,126.092
DI7: E8.A10 J2.A26 J4.A7 MT4.7 | length 133.1
  Top Layer w0.254: J4.A7@220.142,3.354 221.373,4.585 221.373,11.333 231.434,21.394 231.434,83.178 E8.A10@229.612,85 E8.A10@229.612,90 221.373,98.239 221.373,114.701 MT4.7@220.142,115.932 221.373,117.163 221.373,124.861 J2.A26@220.142,126.092
DI8: E8.A9 J2.A25 J4.A8 MT4.8 | length 132.3
  Top Layer w0.254: J4.A8@217.602,3.354 218.833,4.585 218.833,12.101 227.934,21.202 227.934,83.178 E8.A9@226.112,85 E8.A9@226.112,90 218.833,97.279 218.833,114.701 MT4.8@217.602,115.932 218.833,117.163 218.833,124.861 J2.A25@217.602,126.092
DI9: E8.A8 J2.A24 J4.A9 MT4.9 | length 131.5
  Top Layer w0.254: J4.A9@215.062,3.354 216.293,4.585 216.293,13.061 224.434,21.202 224.434,83.178 222.612,85 222.612,90 216.293,96.319 216.293,114.701 MT4.9@215.062,115.932 216.293,117.163 216.293,124.861 J2.A24@215.062,126.092
DI10: E8.A7 J2.A23 J4.A10 MT4.10 | length 130.7
  Top Layer w0.254: J4.A10@212.522,3.354 213.753,4.585 213.753,14.021 220.934,21.202 220.934,83.178 219.112,85 219.112,90 213.753,95.359 213.753,114.701 MT4.10@212.522,115.932 213.753,117.163 213.753,124.861 J2.A23@212.522,126.092
DI11: E8.A6 J2.A22 J4.A11 MT4.11 | length 129.9
  Top Layer w0.254: J4.A11@209.982,3.354 211.213,4.585 211.213,14.981 217.434,21.202 217.434,83.178 E8.A6@215.612,85 E8.A6@215.612,90 211.213,94.399 211.213,114.701 MT4.11@209.982,115.932 211.213,117.163 211.213,124.861 J2.A22@209.982,126.092
DI12: E8.A5 J2.A21 J4.A12 MT4.12 | length 129.1
  Top Layer w0.254: J4.A12@207.442,3.354 208.673,4.585 208.673,15.941 213.934,21.202 213.934,83.178 E8.A5@212.112,85 E8.A5@212.112,90 208.673,93.439 208.673,114.701 MT4.12@207.442,115.932 208.673,117.163 208.673,124.861 J2.A21@207.442,126.092
DI13: E8.A4 J2.A20 J4.A13 MT4.13 | length 128.3
  Top Layer w0.254: J4.A13@204.902,3.354 206.133,4.585 206.133,16.901 210.434,21.202 210.434,83.178 E8.A4@208.612,85 E8.A4@208.612,90 206.133,92.479 206.133,114.701 MT4.13@204.902,115.932 206.133,117.163 206.133,124.861 J2.A20@204.902,126.092
DI14: E8.A3 J2.A19 J4.A14 MT4.14 | length 127.5
  Top Layer w0.254: J4.A14@202.362,3.354 203.593,4.585 203.593,17.861 206.934,21.202 206.934,83.178 E8.A3@205.112,85 E8.A3@205.112,90 203.593,91.519 203.593,114.701 MT4.14@202.362,115.932 203.593,117.163 203.593,124.861 J2.A19@202.362,126.092
DI15: E8.A2 J2.A18 J4.A15 MT4.15 | length 126.8
  Top Layer w0.254: J4.A15@199.822,3.354 201.053,4.585 201.053,18.821 203.434,21.202 203.434,83.178 E8.A2@201.612,85 201.612,92.691 201.053,93.25 201.053,114.701 MT4.15@199.822,115.932 201.053,117.163 201.053,124.861 J2.A18@199.822,126.092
